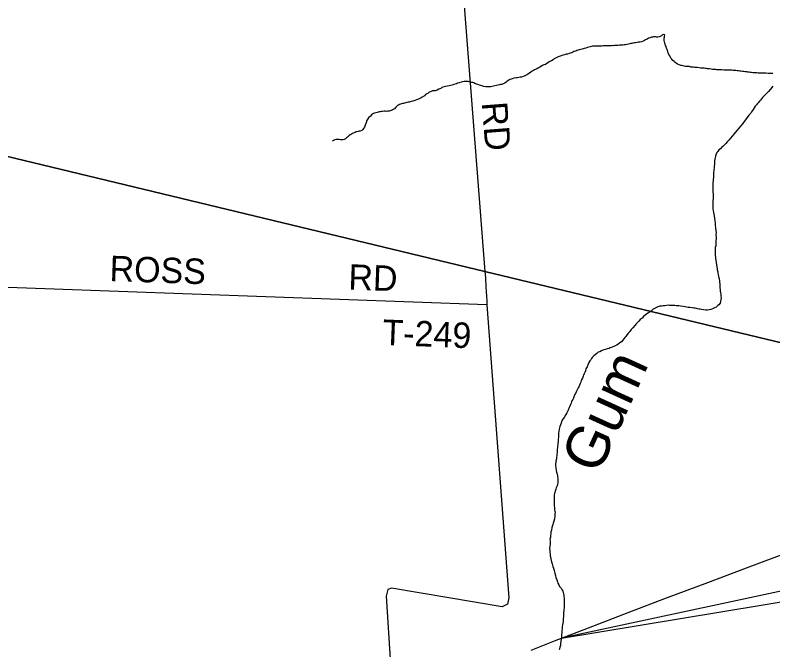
# Model space of a CAD drawing. Extents: x 0.4 to 34.4, y -2.1 to 19.9.
# Drawn here: x 5.402 to 7.097, y 15.372 to 16.79 of the extents above; entities that cross this region are included whole.
import ezdxf

# ---------------------------------------------------------------- set-up
doc = ezdxf.new("R2010")
doc.units = 0
for name, color, linetype in [('GM_X_County_Road', 7, 'Continuous'), ('GM_X_County_Road_Text', 7, 'Continuous'), ('GM_X_Interstate_Route', 7, 'Continuous'), ('GM_X_Minor_River', 7, 'Continuous'), ('GM_X_Minor_River_Text', 7, 'Continuous'), ('GM_X_Township', 7, 'Continuous'), ('GM_X_Township_Road', 7, 'Continuous'), ('GM_X_Township_Road_Text', 7, 'Continuous'), ('SH_Data', 7, 'Continuous')]:
    doc.layers.add(name, color=color, linetype=linetype)

msp = doc.modelspace()

# ---------------------------------------------------------------- linework, layer by layer
at = {"layer": 'GM_X_County_Road'}
for points in [[(6.3625, 17.3767), (6.4528, 16.2176), (6.4539, 16.203)], [(6.4539, 16.203), (6.4539, 16.2029), (6.4553, 16.1829)], [(6.4553, 16.1829), (6.4553, 16.1828), (6.4575, 16.1516), (6.4573, 16.1428), (6.5066, 15.488), (6.5033, 15.474), (6.4918, 15.4678), (6.2441, 15.51), (6.2361, 15.5067), (6.232, 15.492), (6.2416, 15.34), (6.2359, 15.3204), (6.2246, 15.3035), (6.208, 15.2886), (6.1821, 15.2819), (5.8983, 15.2045), (5.7135, 15.1423), (5.5589, 15.0776), (5.4835, 15.0426), (5.4621, 15.035), (5.453, 15.0352), (5.438, 15.0411), (5.4094, 15.0538)]]:
    msp.add_lwpolyline(points, dxfattribs=at)
at = {"layer": 'GM_X_Interstate_Route'}
msp.add_lwpolyline([(6.5561, 15.3712), (6.6089, 15.3922), (6.6849, 15.421), (6.7735, 15.455), (6.8594, 15.4879), (6.9514, 15.5226), (7.0377, 15.555), (7.1358, 15.592)], dxfattribs=at)
at = {"layer": 'GM_X_Minor_River'}
for points in [[(6.8551, 16.7467), (6.8521, 16.7471), (6.8498, 16.7464), (6.8478, 16.7441), (6.8451, 16.7427), (6.8424, 16.7416), (6.8398, 16.7412), (6.8367, 16.7413), (6.8344, 16.7417), (6.8322, 16.7421), (6.8299, 16.7418), (6.8276, 16.7415), (6.8253, 16.7411), (6.8222, 16.74), (6.8191, 16.739), (6.8156, 16.7364), (6.8122, 16.7349), (6.8098, 16.7334), (6.8068, 16.7319), (6.8033, 16.7309), (6.7991, 16.7302), (6.7964, 16.7299), (6.7937, 16.7291), (6.7895, 16.7285), (6.7872, 16.7281), (6.7838, 16.7274), (6.7815, 16.7271), (6.7792, 16.7267), (6.7769, 16.726), (6.7742, 16.7253), (6.7704, 16.7246), (6.7677, 16.7243), (6.7643, 16.724), (6.7616, 16.7233), (6.7582, 16.7233), (6.7543, 16.723), (6.7501, 16.7227), (6.7467, 16.7224), (6.7429, 16.7225), (6.7406, 16.7221), (6.7379, 16.7222), (6.7356, 16.7218), (6.7326, 16.7219), (6.7295, 16.7219), (6.7272, 16.722), (6.7238, 16.7217), (6.7208, 16.7217), (6.7177, 16.7214), (6.7143, 16.7211), (6.7112, 16.7211), (6.7082, 16.7208), (6.7043, 16.7209), (6.7013, 16.7209), (6.699, 16.721), (6.6963, 16.7207), (6.6933, 16.7207), (6.6883, 16.7197), (6.6852, 16.719), (6.6825, 16.7182), (6.6787, 16.7164), (6.6752, 16.7157), (6.6729, 16.715), (6.6706, 16.7143), (6.6668, 16.7132), (6.6637, 16.7125), (6.6614, 16.7118), (6.6584, 16.7111), (6.6561, 16.71), (6.6518, 16.7089), (6.6495, 16.7078), (6.6464, 16.706), (6.6438, 16.7056), (6.6411, 16.7049), (6.638, 16.7035), (6.6349, 16.7028), (6.6307, 16.7013), (6.6272, 16.7006), (6.6234, 16.6995), (6.6192, 16.6981), (6.6165, 16.697), (6.6138, 16.6959), (6.6107, 16.6941), (6.6076, 16.6926), (6.6053, 16.6907), (6.6018, 16.6885), (6.5995, 16.6874), (6.5968, 16.6859), (6.5933, 16.6837), (6.5883, 16.6804), (6.5848, 16.6793), (6.5814, 16.6775), (6.5759, 16.6742), (6.5736, 16.6723), (6.5713, 16.6716), (6.569, 16.6701), (6.5663, 16.669), (6.564, 16.6679), (6.5617, 16.6668), (6.5586, 16.665), (6.5559, 16.6631), (6.5528, 16.6605)], [(7.0972, 16.6601), (7.0934, 16.6601), (7.0907, 16.6602), (7.0865, 16.6603), (7.0812, 16.6604), (7.0789, 16.6608), (7.0766, 16.6604), (7.0743, 16.6605), (7.072, 16.6605), (7.0671, 16.6606), (7.064, 16.6607), (7.0614, 16.6611), (7.0579, 16.6612), (7.0553, 16.6616), (7.0522, 16.6616), (7.0496, 16.6621), (7.0469, 16.6625), (7.0443, 16.6626), (7.0412, 16.663), (7.0389, 16.6634), (7.0351, 16.6639), (7.0321, 16.6643), (7.0291, 16.6647), (7.0256, 16.6652), (7.023, 16.6652), (7.0199, 16.6657), (7.0173, 16.6661), (7.0142, 16.6665), (7.0112, 16.667), (7.0085, 16.667), (7.0051, 16.6671), (7.0024, 16.6675), (6.9998, 16.6676), (6.9975, 16.6676), (6.994, 16.6677), (6.9914, 16.6677), (6.9872, 16.6674), (6.983, 16.6679), (6.9803, 16.6679), (6.9777, 16.668), (6.9746, 16.668), (6.9719, 16.6684), (6.9697, 16.6685), (6.9666, 16.6685), (6.9643, 16.669), (6.962, 16.669), (6.959, 16.6698), (6.9556, 16.6703), (6.9533, 16.6707), (6.951, 16.6707), (6.9487, 16.6708), (6.9465, 16.6712), (6.943, 16.6716), (6.9392, 16.6717), (6.9362, 16.6721), (6.9324, 16.6726), (6.9278, 16.6731), (6.9248, 16.6735), (6.9221, 16.6735), (6.9198, 16.674), (6.9176, 16.674), (6.9137, 16.6744), (6.9103, 16.6753), (6.9077, 16.6753), (6.905, 16.6758), (6.9016, 16.6758), (6.8989, 16.6766), (6.8963, 16.6771), (6.8936, 16.6775), (6.8909, 16.6779), (6.8875, 16.6791), (6.8838, 16.6811), (6.8808, 16.683), (6.8785, 16.6846), (6.8759, 16.6869), (6.8733, 16.6893), (6.8711, 16.692), (6.8688, 16.6943), (6.8677, 16.6966), (6.8663, 16.6993), (6.8644, 16.7024), (6.863, 16.7058), (6.8619, 16.7089), (6.8605, 16.7135), (6.859, 16.7169), (6.8584, 16.7204), (6.8569, 16.7227), (6.8558, 16.7257), (6.8551, 16.728), (6.8544, 16.7307), (6.8541, 16.7334), (6.8541, 16.736), (6.8542, 16.7387), (6.8546, 16.7413), (6.8547, 16.7436), (6.8551, 16.7467)], [(6.5528, 16.6605), (6.5489, 16.6587), (6.5466, 16.6572), (6.5439, 16.6557), (6.5408, 16.6543), (6.5381, 16.6532), (6.5347, 16.6521), (6.532, 16.6514), (6.5289, 16.6507), (6.5255, 16.6503), (6.5228, 16.6504), (6.5174, 16.6494), (6.5136, 16.6483), (6.5113, 16.6476), (6.509, 16.6465), (6.5063, 16.6454), (6.5028, 16.6428), (6.5001, 16.6405), (6.4977, 16.6383), (6.4939, 16.6368), (6.4904, 16.6354), (6.4881, 16.6351), (6.4855, 16.6343), (6.4816, 16.6336), (6.4786, 16.6333), (6.4751, 16.6322), (6.4721, 16.6319), (6.469, 16.6308), (6.4663, 16.6305), (6.464, 16.6302), (6.4606, 16.6302), (6.4575, 16.6303), (6.4552, 16.6303), (6.4503, 16.6312), (6.4461, 16.6324), (6.4439, 16.6328), (6.4405, 16.634), (6.4367, 16.6356), (6.4344, 16.6364), (6.4318, 16.6372), (6.4284, 16.6388), (6.4257, 16.6396), (6.4234, 16.64), (6.4212, 16.6405), (6.4177, 16.6413), (6.4151, 16.6417), (6.4117, 16.6422), (6.4086, 16.6422), (6.4063, 16.6419), (6.4025, 16.6412), (6.3998, 16.6405), (6.396, 16.6394), (6.3917, 16.638), (6.3894, 16.6372), (6.3864, 16.6362), (6.3833, 16.6351), (6.3795, 16.634), (6.3756, 16.6329), (6.3726, 16.6322), (6.3687, 16.6315), (6.3649, 16.6308), (6.3614, 16.6301), (6.3591, 16.6294), (6.3568, 16.6283), (6.3541, 16.6265), (6.3518, 16.6257), (6.3495, 16.6246), (6.346, 16.6224), (6.3414, 16.6214), (6.3387, 16.621), (6.3357, 16.6211), (6.3326, 16.62), (6.3303, 16.6193), (6.3272, 16.6174), (6.3249, 16.6156), (6.3226, 16.6145), (6.3203, 16.613), (6.3179, 16.61), (6.3129, 16.6074), (6.3102, 16.6056), (6.3075, 16.6041), (6.3044, 16.6026), (6.3021, 16.6019), (6.2998, 16.6008), (6.2959, 16.5998), (6.2913, 16.5983), (6.2879, 16.5976), (6.2837, 16.5962), (6.281, 16.5958), (6.2783, 16.5951), (6.276, 16.5944), (6.2729, 16.5937), (6.2706, 16.593), (6.2683, 16.5927), (6.2641, 16.5916), (6.2618, 16.5909), (6.2595, 16.5894), (6.2572, 16.5883), (6.2537, 16.5849), (6.2505, 16.5812), (6.2478, 16.5797)], [(7.0973, 16.6315), (7.0914, 16.6248), (7.0871, 16.6199), (7.0828, 16.6154), (7.0797, 16.6121), (7.077, 16.6091), (7.0742, 16.6061), (7.0695, 16.6005), (7.0668, 16.5982), (7.0656, 16.5956), (7.0625, 16.5926), (7.0602, 16.59), (7.0574, 16.5866), (7.055, 16.5832), (7.0527, 16.5795), (7.0491, 16.5746), (7.0475, 16.5716), (7.0436, 16.5671), (7.0397, 16.5618), (7.0361, 16.5562), (7.033, 16.5524), (7.0295, 16.5479), (7.0244, 16.5419), (7.0209, 16.5378), (7.0169, 16.5333), (7.013, 16.5284), (7.0095, 16.5243), (7.006, 16.5198), (7.0021, 16.5153), (6.9985, 16.5112)], [(6.2478, 16.5797), (6.2455, 16.5782), (6.2432, 16.5775), (6.239, 16.5757), (6.2352, 16.5754), (6.2321, 16.5751), (6.2298, 16.5755), (6.2272, 16.5755), (6.2237, 16.5752), (6.221, 16.5749), (6.2187, 16.5745), (6.2161, 16.5742), (6.2119, 16.5731), (6.2088, 16.5721), (6.2057, 16.571), (6.2034, 16.5703), (6.1995, 16.5673), (6.1968, 16.5647), (6.1925, 16.5609), (6.1913, 16.5587), (6.1894, 16.5564), (6.1882, 16.5542), (6.1877, 16.5519), (6.1865, 16.5481), (6.1853, 16.5447), (6.1833, 16.5402), (6.1813, 16.5372), (6.1801, 16.5349), (6.1774, 16.5327), (6.1739, 16.5312), (6.1713, 16.5309), (6.169, 16.5306), (6.1651, 16.5295), (6.1624, 16.5284), (6.1601, 16.5273), (6.157, 16.5262), (6.1547, 16.5247), (6.1516, 16.5225), (6.1485, 16.5203), (6.1458, 16.518), (6.1435, 16.5158), (6.1407, 16.5136), (6.138, 16.5121), (6.135, 16.5114), (6.1327, 16.5114), (6.1296, 16.5119), (6.127, 16.5123), (6.1247, 16.5127), (6.1224, 16.5128), (6.1201, 16.5124), (6.1174, 16.5117), (6.1144, 16.5102), (6.112, 16.5088)], [(6.9985, 16.5112), (6.995, 16.5071), (6.9915, 16.5034), (6.9887, 16.5004), (6.9849, 16.497), (6.9821, 16.4944), (6.9798, 16.4918), (6.9763, 16.4892), (6.9736, 16.4858), (6.972, 16.4832), (6.97, 16.4794), (6.9687, 16.4749), (6.9679, 16.4722), (6.9671, 16.468), (6.9666, 16.4654), (6.9665, 16.4623), (6.9664, 16.457), (6.9659, 16.4521), (6.9655, 16.4487), (6.965, 16.4452), (6.9649, 16.4422), (6.9645, 16.4395), (6.9641, 16.4365), (6.9639, 16.4308), (6.9639, 16.4274), (6.9634, 16.424), (6.9633, 16.4202), (6.9628, 16.4164), (6.9631, 16.4126), (6.9631, 16.4095), (6.9629, 16.4027), (6.9628, 16.3985), (6.9631, 16.3958), (6.9634, 16.3901), (6.9637, 16.3855), (6.9636, 16.3814), (6.963, 16.3745), (6.963, 16.3707), (6.9629, 16.3681), (6.9628, 16.365), (6.9627, 16.3612), (6.963, 16.3566), (6.9637, 16.3536), (6.9644, 16.3494), (6.9651, 16.3456), (6.9657, 16.3421), (6.9664, 16.3368), (6.967, 16.3307), (6.9677, 16.3261), (6.9679, 16.3212), (6.969, 16.3151), (6.9696, 16.3082), (6.9699, 16.3044), (6.9697, 16.2987), (6.97, 16.2941), (6.9699, 16.2914), (6.9698, 16.2861), (6.9698, 16.2831), (6.9693, 16.2797), (6.9692, 16.2751), (6.9683, 16.2709), (6.9679, 16.2679), (6.9678, 16.2652), (6.9677, 16.2595), (6.9683, 16.2534), (6.9686, 16.2496), (6.9686, 16.247), (6.9696, 16.242), (6.9703, 16.2386), (6.9713, 16.2317), (6.9716, 16.229), (6.9726, 16.2214), (6.974, 16.2168), (6.9739, 16.2141), (6.9746, 16.2103), (6.9757, 16.2073), (6.9764, 16.2034), (6.9771, 16.2008), (6.9777, 16.1969), (6.978, 16.1935), (6.9783, 16.1901), (6.9783, 16.1863), (6.9785, 16.1817), (6.9792, 16.1768), (6.9795, 16.1733), (6.9802, 16.1695), (6.9805, 16.1665), (6.9808, 16.1634), (6.9811, 16.1588), (6.9806, 16.1547), (6.9797, 16.1501), (6.9789, 16.1467), (6.9765, 16.1433), (6.9738, 16.1411), (6.9703, 16.1377), (6.9661, 16.1359), (6.9618, 16.1337), (6.958, 16.1322), (6.9549, 16.1315), (6.9511, 16.1312), (6.9469, 16.1313)], [(6.9469, 16.1313), (6.9416, 16.1318), (6.9374, 16.1326), (6.9347, 16.1331), (6.9321, 16.1335), (6.9287, 16.1339), (6.926, 16.1344), (6.9234, 16.1352), (6.9199, 16.1356), (6.9169, 16.1364), (6.9116, 16.1373), (6.9078, 16.1373), (6.904, 16.1378), (6.9006, 16.1386), (6.8964, 16.1391), (6.8907, 16.1399), (6.8865, 16.1404), (6.8835, 16.1408), (6.8804, 16.1409), (6.8774, 16.1413), (6.8743, 16.1414), (6.8697, 16.1418), (6.8659, 16.1415), (6.8625, 16.142), (6.8591, 16.1417), (6.8552, 16.141), (6.8518, 16.1407), (6.8484, 16.1403), (6.8445, 16.1396), (6.8395, 16.1382), (6.8365, 16.1371), (6.8326, 16.1349), (6.8295, 16.1331), (6.8245, 16.129), (6.8202, 16.1256), (6.8175, 16.1245), (6.8144, 16.1219), (6.8113, 16.1197), (6.8078, 16.1171), (6.8043, 16.1134), (6.8004, 16.11), (6.7969, 16.1063), (6.7942, 16.1037), (6.7914, 16.1003), (6.7891, 16.0973), (6.784, 16.0917), (6.7801, 16.0876), (6.7773, 16.0834), (6.7742, 16.0801), (6.7711, 16.0763), (6.7683, 16.0722), (6.766, 16.0696), (6.764, 16.0669), (6.7612, 16.0639), (6.7581, 16.0606), (6.755, 16.058), (6.7508, 16.055), (6.7477, 16.0531), (6.7442, 16.0513), (6.7415, 16.0498), (6.7373, 16.048), (6.7334, 16.0469), (6.7307, 16.0455), (6.7261, 16.0444), (6.723, 16.0433), (6.72, 16.0426), (6.7169, 16.0415), (6.7134, 16.0401), (6.71, 16.0382), (6.7065, 16.0368), (6.7034, 16.0345), (6.6999, 16.0319), (6.6968, 16.0293), (6.6929, 16.0256), (6.6913, 16.023), (6.6901, 16.0203), (6.6874, 16.0181), (6.6854, 16.0143), (6.6838, 16.0106), (6.6814, 16.0045), (6.679, 15.9996), (6.6777, 15.9954), (6.6765, 15.9917), (6.6749, 15.989), (6.6737, 15.9864), (6.6729, 15.9834), (6.6713, 15.9792), (6.6693, 15.9754), (6.6681, 15.9728), (6.6673, 15.9701), (6.6661, 15.9671), (6.6644, 15.9637), (6.6628, 15.9599), (6.6616, 15.9573), (6.6593, 15.9532), (6.6577, 15.9502), (6.6553, 15.9449), (6.6541, 15.9422), (6.6529, 15.9396), (6.6508, 15.9343), (6.6492, 15.9317)], [(6.6492, 15.9317), (6.6476, 15.9286), (6.6468, 15.926), (6.6456, 15.923), (6.6444, 15.92), (6.6428, 15.9162), (6.6416, 15.9132), (6.6392, 15.9075), (6.6376, 15.9049), (6.636, 15.9018), (6.6336, 15.8977), (6.6304, 15.8909), (6.6273, 15.8872), (6.6245, 15.8823), (6.6233, 15.8785), (6.6217, 15.8747), (6.6208, 15.8713), (6.6192, 15.8652), (6.6183, 15.8607), (6.6178, 15.8561), (6.6178, 15.8535), (6.6176, 15.8489), (6.6172, 15.8463), (6.6171, 15.8432), (6.6166, 15.8379), (6.6161, 15.833), (6.6161, 15.8299), (6.6156, 15.8269), (6.6152, 15.8235), (6.6147, 15.8204), (6.6146, 15.8162), (6.6142, 15.8121), (6.6141, 15.8094), (6.6136, 15.8064), (6.6132, 15.8014), (6.6127, 15.7988), (6.6118, 15.7938), (6.6114, 15.7912), (6.6109, 15.7878), (6.6109, 15.7843), (6.6115, 15.779), (6.6125, 15.7729), (6.6132, 15.7691), (6.6142, 15.7645), (6.6153, 15.7614), (6.6156, 15.7588), (6.6163, 15.7553), (6.6162, 15.7523), (6.6158, 15.7489), (6.6157, 15.7451), (6.6153, 15.742), (6.6144, 15.7386), (6.6124, 15.7337), (6.6112, 15.7307), (6.6099, 15.7265), (6.6095, 15.7239), (6.6083, 15.7212), (6.6079, 15.7182), (6.6078, 15.7151), (6.6077, 15.7117), (6.6076, 15.7079), (6.6075, 15.7045), (6.6078, 15.6984), (6.6081, 15.6946), (6.6087, 15.6885), (6.6086, 15.6851), (6.6093, 15.682), (6.6097, 15.6793), (6.6096, 15.6763), (6.6095, 15.6706), (6.6082, 15.6649), (6.6069, 15.6592), (6.6057, 15.6547), (6.6045, 15.6517), (6.6036, 15.6479), (6.6028, 15.6452), (6.6015, 15.6395), (6.6007, 15.6354), (6.6006, 15.6327), (6.5993, 15.627), (6.5993, 15.6236), (6.5984, 15.6187), (6.5987, 15.6156), (6.5986, 15.6118), (6.5985, 15.608), (6.598, 15.6035), (6.5975, 15.5981), (6.5978, 15.5943), (6.5981, 15.5905), (6.5988, 15.5856), (6.5991, 15.5829), (6.6001, 15.5753), (6.6018, 15.5684), (6.6033, 15.5642), (6.605, 15.5584), (6.6065, 15.5542), (6.6079, 15.5492), (6.6093, 15.5435), (6.6107, 15.5382), (6.6117, 15.5339), (6.6139, 15.5282)], [(6.6139, 15.5282), (6.6149, 15.524), (6.616, 15.5209), (6.6179, 15.5175), (6.6197, 15.5133), (6.6238, 15.5094), (6.6252, 15.5067), (6.6271, 15.5028), (6.6278, 15.5002), (6.6284, 15.4967), (6.6295, 15.4937), (6.6298, 15.491), (6.6301, 15.4868), (6.63, 15.4826), (6.6303, 15.4792), (6.6299, 15.4765), (6.6302, 15.472), (6.6301, 15.4693), (6.63, 15.4663), (6.6295, 15.4602), (6.629, 15.4537), (6.6288, 15.4461), (6.6283, 15.4404), (6.6282, 15.4351), (6.6265, 15.4275), (6.626, 15.4233), (6.6256, 15.4188), (6.6251, 15.4161), (6.6251, 15.4135), (6.6246, 15.4108), (6.6245, 15.4051), (6.624, 15.3986), (6.623, 15.391), (6.6221, 15.3857), (6.6217, 15.3816), (6.6208, 15.3778), (6.62, 15.3744), (6.6192, 15.3717)]]:
    msp.add_lwpolyline(points, dxfattribs=at)
at = {"layer": 'GM_X_Township'}
for points in [[(5.0712, 17.1497), (5.0993, 16.7069), (5.1117, 16.5403), (6.4528, 16.2176), (7.8323, 15.8856)], [(7.8323, 15.8856), (6.4528, 16.2176), (5.1117, 16.5403)]]:
    msp.add_lwpolyline(points, dxfattribs=at)
at = {"layer": 'GM_X_Township_Road'}
msp.add_lwpolyline([(6.4573, 16.1428), (5.1378, 16.1909)], dxfattribs=at)
at = {"layer": 'SH_Data'}
msp.add_lwpolyline([(10.4047, 16.0223), (10.4047, 16.2068), (6.6239, 15.3979)], close=True, dxfattribs=at)

# ---------------------------------------------------------------- texts
at = {"layer": 'GM_X_County_Road_Text'}
msp.add_text('RD', height=0.05682, rotation=274.4378, dxfattribs=at).set_placement((6.4458, 16.5947))
at = {"layer": 'GM_X_Minor_River_Text'}
msp.add_text('Gum', height=0.09471, rotation=65.5352, dxfattribs=at).set_placement((6.7066, 15.7611))
at = {"layer": 'GM_X_Township_Road_Text'}
for s, rotation, p in [('ROSS', 358.0725, (5.6126, 16.1961)), ('RD', 358.0243, (6.1468, 16.177)), ('T-249', 357.7534, (6.223, 16.0536))]:
    msp.add_text(s, height=0.05682, rotation=rotation, dxfattribs=at).set_placement(p)

doc.saveas('drawing.dxf')
